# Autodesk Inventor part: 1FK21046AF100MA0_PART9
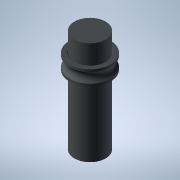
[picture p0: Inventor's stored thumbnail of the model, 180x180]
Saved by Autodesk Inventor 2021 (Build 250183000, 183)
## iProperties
Created: 2025-04
Part Number: 1FK21046AF100MA0_PART9
Material: Generic
Catalog Web Link: www.3dfindit.com
Description: -Servo synchronous motor
Document SubType Name: Modeling
Designer: psAdmin
Mass: 18.6788 g
Surface Area: 52.316 cm^2
Volume: 18.6788 cm^3
Density: 1 g/cm^3
Appearance: PSOLRGB-212-217-219
Category: PARTsolutions
Title: 1FK21046AF100MA0_PART9
Author: Cadenas PARTsolutions
Comments: Servo synchronous motor
Sending System: PARTsolutions
Preprocessor: ST-DEVELOPER v19.3
PSOL_IDENT_0: {$CADENAS_DATA/23d-libs/siemens_ag/_cat_/4f/2b/1fk21046af100ma0.prj},213 {VTYP=3D},{NB=1FK21046AF100
PSOL_IDENT_1: MA0_PART9},{LINA=1FK21046AF100MA0_PART9},{NN=1FK21046AF100MA0_PART9},{NOPRJ=TRUE},{DATE=19.08.2025 1
PSOL_IDENT_2: 4:00:37},{GEOMDATE=30.07.2025 02:01:06},{VERSION=},{LINEID=10},{WBVAR=},{WBNUMERIC=}  {NB=1FK21046AF
PSOL_IDENT_3: 100MA0_PART9},{LINA=1FK21046AF100MA0_PART9},{KT=DUMMY},{PREVIEW=../../../_pool_/cb/72/p_d211_xx_0043
PSOL_IDENT_4: 4j.png},{DESCSHORT=SIMOTICS S-1FK2 HD, SINAMICS S210 3AC 400V-480V, 3.2 Nm, 3000 rpm},{DESCLONG=SIMO
PSOL_IDENT_5: TICS S-1FK2 HD servo motor M0=3.2 Nm; PN = 1 kW at nN=3000 rpm (380-480 V); PN = 0.5 kW at nN=1500 r
PSOL_IDENT_6: pm (200-240 V); with holding brake; degree of protection IP64; cylindrical shaft D19x40mm; absolute
PSOL_IDENT_7: encoder 22-bit + 12-bit multiturn (encoder AM22DQC); with OCC interface; plug size M17, rotatable; S
PSOL_IDENT_8: IMOTICS S-1FK2 servomotorfor a wide range of uses in industrial environments. SIMOTICS S‑1FK2 servom
PSOL_IDENT_9: otors are compact synchronous motors with a high dynamic performance that set themselves apart as a
PSOL_IDENT_10: result of their high power density, degree of protection and overload capability. The motors are ava
PSOL_IDENT_11: ilable in two variants: as High Dynamic variant (highest dynamic performance as a result of the low
PSOL_IDENT_12: intrinsic moment of inertia for applications demanding a high dynamic performance with low moved mas
PSOL_IDENT_13: ses) - and as Compact variant (precise and stable closed-loop control for medium up to large moved m
PSOL_IDENT_14: asses as a result of a medium intrinsic moment of inertia). SIMOTICSS‑1FK2 servomotors fully exploit
PSOL_IDENT_15: their strengths in a system with the SINAMICSS210 frequency converter and simple connection using t
PSOL_IDENT_16: he one cable connection (OCC). Advantages include the short control and positioning times, fast and
PSOL_IDENT_17: precise correction of disturbing quantities as well as stable control with a high dynamic performanc
PSOL_IDENT_18: e. The servo motors can be configured to address a wide range of requirements. For example with and
PSOL_IDENT_19: without holding brake, IP64 or IP65 degree of protection, singleturn or multiturn absolute encoders
PSOL_IDENT_20: - to name just a few. Further, the servomotors are available in different shaft heights extending fr
PSOL_IDENT_21: om 20 to 100. A shaft sealing ring is available to achieve an IP65 degree of protection and for subs
PSOL_IDENT_22: equent mounting at the motor or as spare part. SIMOTICS - the optimum motor for each and every motio
PSOL_IDENT_23: n control application.},{INTNO=195125049673},{SUPPLIERALTNO=1FK2104-6AF10-0MA0},{MANUID=1FK21046AF10
PSOL_IDENT_24: 0MA0},{MANUNAME=Siemens},{MANUTYPEDESC=Synchronous motor 1FK2-HD 3.2 NM},{AAU732=SIMOTICS},{AAO057=S
PSOL_IDENT_25: -1FK2},{AAU734=SIMOTICS S-1FK2 HD servo motor M0=3.2 Nm; PN = 1 kW at nN=3000 rpm (380-480 V); PN =
PSOL_IDENT_26: 0.5 kW at nN=1500 rpm (200-240 V); with holding brake; degree of protection IP64; cylindrical shaft
PSOL_IDENT_27: D19x40mm; absolute encoder 22-bit + 12-bit multiturn (encoder AM22DQC); with OCC interface; plug siz
PSOL_IDENT_28: e M17, rotatable;},{AAW338=Synchronous motor 1FK2-HD 3.2 NM},{AAO742=SIMOTICS},{AAO663=4042948694534
PSOL_IDENT_29: },{NOCUPEROU=1},{PRICEQUANTITY=1},{QUANTITYMIN=1},{QUANTITYINT=1},{CTN=85015220},{COO=DE},{AAO676=1F
PSOL_IDENT_30: K2104-6AF10-0MA0},{AAO677=Siemens AG},{ORDERUNIT=C62},{CONTENTUNIT=C62}
NB: 1FK21046AF100MA0_PART9
NT: Servo synchronous motor
NBSYN: $MANUID._PART9
LINA: 1FK21046AF100MA0_PART9
CATALOG: SIEMENS
PREVIEW: ../../../_pool_/cb/72/p_d211_xx_00434j.png
DESCSHORT: SIMOTICS S-1FK2 HD, SINAMICS S210 3AC 400V-480V, 3.2 Nm, 3000 rpm
DESCLONG: SIMOTICS S-1FK2 HD servo motor M0=3.2 Nm; PN = 1 kW at nN=3000 rpm (380-480 V); PN = 0.5 kW at nN=1500 rpm (200-240 V); with holding brake; degree of protection
INTNO: 195125049673
SUPPLIERALTNO: 1FK2104-6AF10-0MA0
MANUID: 1FK21046AF100MA0
MANUNAME: Siemens
MANUTYPEDESC: Synchronous motor 1FK2-HD 3.2 NM
AAU732: SIMOTICS
AAO057: S-1FK2
AAU734: SIMOTICS S-1FK2 HD servo motor M0=3.2 Nm; PN = 1 kW at nN=3000 rpm (380-480 V); PN = 0.5 kW at nN=1500 rpm (200-240 V); with holding brake; degree of protection
AAW338: Synchronous motor 1FK2-HD 3.2 NM
AAO742: SIMOTICS
AAO663: 4042948694534.0
NOCUPEROU: 1
PRICEQUANTITY: 1
QUANTITYMIN: 1
QUANTITYINT: 1
CTN: 85015220
COO: DE
ARTICLENO: 1FK21046AF100MA0_PART9
BOMINFO: 1FK21046AF100MA0_PART9
CREATOR: CADENAS GmbH
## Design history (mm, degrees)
feature "2025_04_17_14_59_39_0177"
body "Solid1"
